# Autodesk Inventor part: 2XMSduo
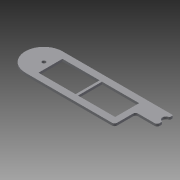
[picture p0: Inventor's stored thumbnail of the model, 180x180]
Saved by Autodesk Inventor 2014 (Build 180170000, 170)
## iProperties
Created: 2015-01
Part Number: 2XMSduo
Material: Generic
Document SubType Name: Modeling
Designer: Drano
Density: 1 g/cm^3
Appearance: Default
Author: Drano
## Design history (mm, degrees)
sketch "Sketch1"
  geometry: L1 (-38.432, -15.474)-(34.068, -15.474); L2 (-38.432, 15.526)-(53.068, 15.526); L3 (0.068, -9.974)-(0.068, 10.026); L4 (0.068, 10.026)-(31.068, 10.026); L5 (31.068, -9.974)-(31.068, 10.026); L6 (0.068, -9.974)-(31.068, -9.974); L7 (-32.932, -9.974)-(-32.932, 10.026); L8 (-32.932, 10.026)-(-1.932, 10.026); L9 (-1.932, -9.974)-(-1.932, 10.026); L10 (-32.932, -9.974)-(-1.932, -9.974); L11 (54.068, 4.026)-(54.068, 5.653); L12 (54.068, 13.399)-(54.068, 14.526); L13 (38.068, 2.026)-(52.068, 2.026); L14 (36.068, -13.474)-(36.068, 0.026); C1 r 1.5 at (-38.432, 0.026); A1 r 15.5 centre (-38.432, 0.026) between (-38.432, 15.526) and (-38.432, -15.474); A2 r 2 centre (34.068, -13.474) between (34.068, -15.474) and (36.068, -13.474); A3 r 1 centre (53.068, 14.526) between (54.068, 14.526) and (53.068, 15.526); A4 r 2 centre (52.068, 4.026) between (52.068, 2.026) and (54.068, 4.026); A5 r 3 centre (54.068, 9.526) between (53.318, 12.431) and (53.318, 6.621); A6 r 1 centre (53.068, 5.653) between (54.068, 5.653) and (53.318, 6.621); A7 r 1 centre (53.068, 13.399) between (53.318, 12.431) and (54.068, 13.399); A8 r 2 centre (38.068, 0.026) between (38.068, 2.026) and (36.068, 0.026); 1 further point
  constraints: 28 end point, 16 point on circle, 9 centre point
extrude "Extrusion1" new body sketch "Sketch1" distance "d0" = 2; taper "d1" = 0 deg
body "Solid1"
